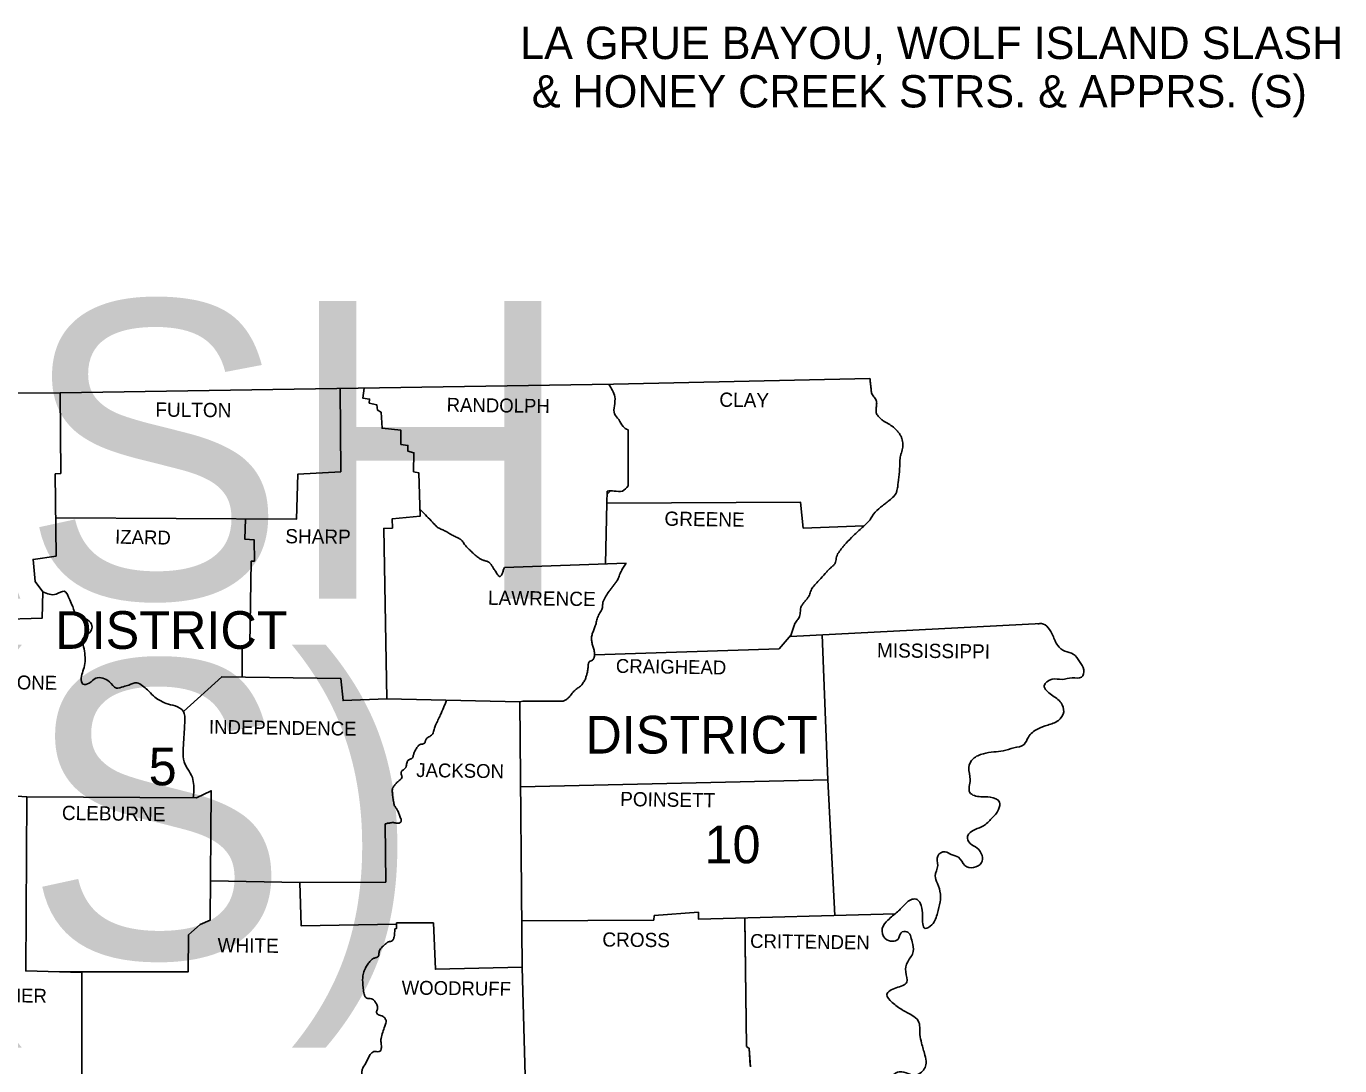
# Model space of a CAD drawing. Extents: x 982240 to 1103002, y 974866 to 1054902.
# Drawn here: x 1087558 to 1101862, y 1040761 to 1052081 of the extents above; entities that cross this region are included whole.
import ezdxf

# ---------------------------------------------------------------- set-up
doc = ezdxf.new("R2010")
doc.units = 0
for name, color, linetype in [('1', 7, 'Continuous'), ('Default', 7, 'Continuous'), ('R_Draft', 7, 'Continuous')]:
    doc.layers.add(name, color=color, linetype=linetype)

msp = doc.modelspace()

# ---------------------------------------------------------------- linework, layer by layer
at = {"layer": '1'}
for p, q in [((1095882, 1045436), (1095921, 1045555)), ((1091591, 1042318), (1091994, 1042318))]:
    msp.add_line(p, q, dxfattribs=at)
for points in [[(1076997, 1048082), (1082818, 1048078), (1087927, 1048089), (1093953, 1048183), (1096746, 1048247)], [(1091238, 1048140), (1091224, 1048031), (1091296, 1048021), (1091293, 1047977), (1091375, 1047959), (1091383, 1047902), (1091422, 1047877), (1091433, 1047704), (1091638, 1047682), (1091638, 1047527), (1091714, 1047517), (1091714, 1047455), (1091779, 1047437), (1091775, 1047229), (1091833, 1047218), (1091847, 1046746), (1091541, 1046717), (1091545, 1046617), (1091451, 1046613), (1091483, 1044755), (1092934, 1044723), (1092959, 1041836), (1092013, 1041811), (1091994, 1042318)], [(1087927, 1048089), (1087934, 1047211), (1087873, 1047207), (1087883, 1046311), (1087631, 1046275), (1087653, 1046033), (1087739, 1045922), (1087732, 1045637), (1087243, 1045619), (1087225, 1045180), (1086778, 1045166), (1086757, 1044633), (1086782, 1044590), (1086793, 1043740), (1087563, 1043690), (1087552, 1041793), (1088164, 1041775), (1088164, 1039845), (1087682, 1039809), (1087646, 1039384), (1086836, 1039381)], [(1095882, 1045436), (1098615, 1045576)], [(1092955, 1042340), (1094392, 1042347), (1094396, 1042397), (1094878, 1042433), (1094878, 1042358), (1097023, 1042417)], [(1091591, 1042318), (1091591, 1042257), (1091573, 1042253)]]:
    msp.add_lwpolyline(points, dxfattribs=at)
for points in [[(1096746, 1048247), (1096750, 1048208), (1096754, 1048168), (1096759, 1048128), (1096764, 1048089), (1096773, 1048067), (1096787, 1048047), (1096803, 1048027), (1096815, 1048006), (1096819, 1047970), (1096815, 1047930), (1096812, 1047891), (1096815, 1047872), (1096822, 1047855), (1096849, 1047820), (1096883, 1047790), (1096909, 1047773), (1096936, 1047758), (1096962, 1047743), (1096988, 1047725), (1097040, 1047679), (1097062, 1047652), (1097072, 1047637), (1097081, 1047621), (1097094, 1047591), (1097102, 1047560), (1097105, 1047529), (1097103, 1047499), (1097097, 1047467), (1097088, 1047436), (1097079, 1047404), (1097074, 1047373), (1097072, 1047338), (1097071, 1047302), (1097069, 1047267), (1097067, 1047232), (1097052, 1047110), (1097046, 1047053), (1097040, 1047026), (1097036, 1047012), (1097031, 1046998), (1096993, 1046948), (1096944, 1046908), (1096924, 1046892), (1096903, 1046876), (1096882, 1046860), (1096862, 1046843), (1096786, 1046768), (1096772, 1046748), (1096760, 1046728), (1096747, 1046707), (1096732, 1046689), (1096638, 1046602), (1096545, 1046512), (1096469, 1046433), (1096449, 1046409), (1096429, 1046384), (1096411, 1046358), (1096394, 1046332), (1096383, 1046305), (1096377, 1046275), (1096371, 1046246), (1096366, 1046233), (1096358, 1046221), (1096338, 1046200), (1096316, 1046181), (1096295, 1046162), (1096275, 1046141), (1096210, 1046069), (1096124, 1045972), (1096109, 1045950), (1096100, 1045925), (1096091, 1045899), (1096080, 1045875), (1096061, 1045847), (1096039, 1045820), (1096016, 1045793), (1095998, 1045763), (1095990, 1045738), (1095988, 1045710), (1095986, 1045682), (1095980, 1045655), (1095968, 1045633), (1095954, 1045612), (1095939, 1045591), (1095926, 1045569), (1095921, 1045555)], [(1098575, 1045573), (1098615, 1045576), (1098737, 1045447), (1098791, 1045339), (1098870, 1045277), (1098960, 1045245), (1099029, 1045162), (1099076, 1045072), (1099050, 1044993), (1098950, 1044986), (1098838, 1044968), (1098730, 1044971), (1098644, 1044899), (1098723, 1044802), (1098827, 1044712), (1098856, 1044615), (1098798, 1044521), (1098683, 1044471), (1098572, 1044428), (1098471, 1044341), (1098424, 1044259), (1098312, 1044223), (1098197, 1044190), (1098096, 1044179), (1097981, 1044158), (1097870, 1044104), (1097823, 1044010), (1097837, 1043877), (1097834, 1043737), (1097952, 1043690), (1098057, 1043686), (1098158, 1043632), (1098147, 1043553), (1098071, 1043452), (1097981, 1043373), (1097891, 1043333), (1097808, 1043258), (1097837, 1043182), (1097913, 1043132), (1097967, 1043049), (1097960, 1042973), (1097873, 1042919), (1097780, 1042941), (1097711, 1043031), (1097632, 1043060), (1097564, 1043092), (1097484, 1043045), (1097484, 1042941), (1097456, 1042829), (1097481, 1042747), (1097513, 1042631), (1097510, 1042545), (1097481, 1042423), (1097420, 1042297), (1097348, 1042257), (1097319, 1042394), (1097304, 1042505), (1097261, 1042570), (1097204, 1042574), (1097128, 1042520), (1097045, 1042437), (1096941, 1042347), (1096880, 1042257), (1096912, 1042145), (1096991, 1042117), (1097052, 1042138), (1097085, 1042210), (1097146, 1042221), (1097204, 1042109)], [(1091573, 1042253), (1091571, 1042223), (1091568, 1042194), (1091564, 1042164), (1091560, 1042149), (1091558, 1042142), (1091555, 1042135), (1091544, 1042121), (1091525, 1042115), (1091505, 1042110), (1091495, 1042107), (1091487, 1042102), (1091445, 1042065), (1091408, 1042023), (1091401, 1042006), (1091399, 1041986), (1091397, 1041967), (1091390, 1041951), (1091383, 1041945), (1091375, 1041941), (1091358, 1041936), (1091340, 1041931), (1091325, 1041922), (1091308, 1041905), (1091292, 1041887), (1091277, 1041868), (1091264, 1041847), (1091239, 1041796), (1091224, 1041742), (1091221, 1041688), (1091224, 1041634), (1091227, 1041603), (1091231, 1041572), (1091238, 1041542), (1091243, 1041527), (1091249, 1041512), (1091266, 1041497), (1091291, 1041493), (1091318, 1041490), (1091339, 1041479), (1091347, 1041471), (1091353, 1041463), (1091365, 1041445), (1091383, 1041407), (1091384, 1041389), (1091378, 1041369), (1091373, 1041350), (1091375, 1041332), (1091392, 1041316), (1091417, 1041307), (1091443, 1041298), (1091462, 1041281), (1091468, 1041271), (1091474, 1041260), (1091477, 1041249), (1091476, 1041238), (1091462, 1041191), (1091422, 1041058), (1091419, 1041036), (1091421, 1041014), (1091424, 1040991), (1091426, 1040968), (1091424, 1040948), (1091422, 1040938), (1091419, 1040929), (1091400, 1040915), (1091371, 1040915), (1091342, 1040915), (1091321, 1040903), (1091264, 1040806), (1091224, 1040738), (1091219, 1040727), (1091212, 1040693), (1091211, 1040670), (1091210, 1040648), (1091212, 1040632), (1091216, 1040615), (1091220, 1040599), (1091221, 1040583), (1091216, 1040570), (1091207, 1040557), (1091198, 1040545), (1091192, 1040533), (1091189, 1040514), (1091188, 1040494), (1091187, 1040475), (1091181, 1040457), (1091145, 1040392), (1091113, 1040331), (1091114, 1040313), (1091128, 1040295), (1091143, 1040277), (1091149, 1040259), (1091144, 1040234), (1091138, 1040209), (1091132, 1040189), (1091126, 1040169), (1091116, 1040129)], [(1097204, 1042109), (1097218, 1042005), (1097157, 1041893), (1097135, 1041782), (1097146, 1041670), (1097031, 1041609), (1096930, 1041537), (1096988, 1041451), (1097096, 1041371), (1097204, 1041310), (1097272, 1041249), (1097290, 1041101), (1097308, 1041008), (1097344, 1040878), (1097358, 1040788), (1097294, 1040680), (1097218, 1040659), (1097139, 1040684), (1097045, 1040691), (1096970, 1040619), (1096916, 1040518), (1096862, 1040417), (1096822, 1040331), (1096782, 1040237), (1096703, 1040129), (1096606, 1040111), (1096491, 1040083), (1096422, 1040003), (1096433, 1039870), (1096498, 1039780), (1096548, 1039669), (1096584, 1039571), (1096566, 1039449), (1096516, 1039359), (1096451, 1039305), (1096422, 1039190), (1096376, 1039103), (1096332, 1039075), (1096246, 1039082), (1096152, 1039100), (1096073, 1039093), (1095998, 1039053), (1095922, 1039078), (1095843, 1039165), (1095778, 1039229), (1095706, 1039255), (1095630, 1039215), (1095616, 1039096), (1095652, 1038974), (1095684, 1038808), (1095652, 1038707), (1095641, 1038542)]]:
    msp.add_spline(points, degree=3, dxfattribs=at)
at = {"layer": 'Default'}
msp.add_line((1093881, 1046887), (1093885, 1047020), dxfattribs=at)
for points in [[(1090976, 1048136), (1090983, 1047229), (1090515, 1047203), (1090501, 1046714), (1087878, 1046728)], [(1094111, 1047686), (1094111, 1047077)], [(1093866, 1046227), (1093881, 1046887), (1093885, 1046887), (1095990, 1046897), (1096019, 1046617), (1096680, 1046641)], [(1089947, 1046717), (1089939, 1046494), (1090040, 1046487), (1090043, 1046257), (1090007, 1046257), (1089993, 1045349), (1089910, 1045313), (1089910, 1044994)], [(1092765, 1046188), (1094092, 1046235)], [(1093746, 1045237), (1095756, 1045303), (1095889, 1045455)], [(1096227, 1045454), (1096289, 1043873), (1096362, 1042399)], [(1089269, 1044619), (1089687, 1044997), (1090983, 1044979), (1091008, 1044737), (1091483, 1044755)], [(1093406, 1044730), (1092967, 1044730), (1092934, 1044723)], [(1096289, 1043873), (1092942, 1043797)], [(1087563, 1043690), (1089413, 1043679), (1089572, 1043755), (1089561, 1042347), (1089453, 1042300), (1089356, 1042217), (1089323, 1042185), (1089320, 1041782), (1087919, 1041782)], [(1091465, 1043395), (1091473, 1042761), (1090537, 1042757), (1089564, 1042776)], [(1090537, 1042757), (1090551, 1042286), (1091591, 1042304)], [(1095382, 1042372), (1095400, 1040972), (1095432, 1040950), (1095444, 1040751)], [(1095382, 1042358), (1095400, 1040972), (1095432, 1040950), (1095443, 1040763)], [(1095382, 1042358), (1095400, 1040972), (1095432, 1040950), (1095443, 1040763)], [(1095382, 1042358), (1095400, 1040972), (1095432, 1040950), (1095443, 1040763)], [(1095382, 1042358), (1095400, 1040972), (1095432, 1040950), (1095443, 1040763)], [(1092959, 1041836), (1093013, 1039863), (1092157, 1039859), (1092153, 1039780), (1091905, 1039766), (1091883, 1039355), (1091542, 1039355)]]:
    msp.add_lwpolyline(points, dxfattribs=at)
for points in [[(1093902, 1048182), (1093967, 1048046), (1093964, 1047949), (1093964, 1047859), (1094011, 1047797), (1094057, 1047722), (1094111, 1047686)], [(1094111, 1047077), (1094050, 1047020), (1093960, 1047020), (1093885, 1047020)], [(1091845, 1046822), (1091905, 1046759), (1091966, 1046696), (1091974, 1046687), (1091999, 1046661), (1092016, 1046644), (1092025, 1046635), (1092030, 1046631), (1092034, 1046627), (1092053, 1046615), (1092073, 1046606), (1092093, 1046597), (1092113, 1046588), (1092160, 1046561), (1092207, 1046534), (1092228, 1046523), (1092249, 1046513), (1092280, 1046497), (1092285, 1046494), (1092290, 1046491), (1092306, 1046476), (1092318, 1046458), (1092330, 1046439), (1092337, 1046431), (1092344, 1046422), (1092381, 1046384), (1092419, 1046347), (1092438, 1046330), (1092456, 1046315), (1092476, 1046300), (1092495, 1046285), (1092524, 1046270), (1092557, 1046260), (1092588, 1046248), (1092602, 1046239), (1092608, 1046234), (1092614, 1046228), (1092624, 1046213), (1092634, 1046198), (1092643, 1046182), (1092653, 1046167), (1092660, 1046157), (1092667, 1046146), (1092680, 1046125), (1092694, 1046106), (1092701, 1046098), (1092704, 1046094), (1092706, 1046093), (1092707, 1046091), (1092711, 1046088), (1092715, 1046088), (1092724, 1046093), (1092739, 1046118), (1092753, 1046155), (1092759, 1046173), (1092765, 1046188)], [(1094092, 1046235), (1094062, 1046191), (1094036, 1046145), (1094024, 1046120), (1094015, 1046094), (1094005, 1046069), (1093993, 1046044), (1093972, 1046015), (1093950, 1045986), (1093928, 1045958), (1093906, 1045929), (1093871, 1045875), (1093856, 1045846), (1093841, 1045817), (1093836, 1045799), (1093835, 1045780), (1093834, 1045760), (1093831, 1045742), (1093819, 1045716), (1093805, 1045692), (1093791, 1045667), (1093780, 1045641), (1093773, 1045616), (1093766, 1045591), (1093759, 1045565), (1093751, 1045540), (1093744, 1045519), (1093735, 1045497), (1093726, 1045476), (1093719, 1045454), (1093715, 1045432), (1093714, 1045409), (1093716, 1045386), (1093719, 1045364), (1093724, 1045341), (1093731, 1045319), (1093739, 1045296), (1093744, 1045274), (1093746, 1045253), (1093746, 1045232), (1093743, 1045211), (1093740, 1045201), (1093737, 1045191), (1093726, 1045179), (1093709, 1045171), (1093693, 1045164), (1093683, 1045151), (1093680, 1045139), (1093678, 1045126), (1093676, 1045099), (1093673, 1045073), (1093669, 1045047), (1093659, 1045011), (1093647, 1044975), (1093627, 1044937), (1093614, 1044919), (1093600, 1044903), (1093584, 1044888), (1093566, 1044876), (1093548, 1044863), (1093532, 1044849), (1093513, 1044829), (1093496, 1044808), (1093479, 1044786), (1093460, 1044766), (1093435, 1044746), (1093421, 1044738), (1093406, 1044730)], [(1087739, 1045922), (1087883, 1045897), (1087970, 1045929), (1088031, 1045835), (1088063, 1045763), (1088117, 1045659), (1088204, 1045627), (1088269, 1045569), (1088269, 1045508), (1088211, 1045450), (1088168, 1045393), (1088182, 1045324), (1088197, 1045231), (1088197, 1045141), (1088175, 1045058), (1088157, 1044982), (1088175, 1044917), (1088243, 1044928), (1088315, 1044982), (1088391, 1044982), (1088463, 1044943), (1088539, 1044874), (1088614, 1044889), (1088675, 1044907), (1088762, 1044932), (1088823, 1044899), (1088877, 1044856), (1088942, 1044788), (1089003, 1044745), (1089082, 1044705), (1089179, 1044680), (1089269, 1044619), (1089284, 1044514), (1089280, 1044424), (1089273, 1044313), (1089266, 1044190), (1089277, 1044071), (1089316, 1043992), (1089367, 1043899), (1089381, 1043812), (1089377, 1043675)], [(1092134, 1044741), (1092102, 1044659), (1092067, 1044579), (1092054, 1044552), (1092041, 1044525), (1092029, 1044498), (1092016, 1044471), (1092007, 1044448), (1092000, 1044424), (1091993, 1044400), (1091984, 1044377), (1091970, 1044361), (1091952, 1044348), (1091932, 1044337), (1091923, 1044331), (1091915, 1044323), (1091909, 1044312), (1091905, 1044298), (1091901, 1044284), (1091894, 1044273), (1091880, 1044266), (1091863, 1044263), (1091846, 1044260), (1091833, 1044251), (1091826, 1044243), (1091819, 1044235), (1091807, 1044217), (1091796, 1044198), (1091786, 1044179), (1091780, 1044163), (1091775, 1044147), (1091771, 1044130), (1091764, 1044115), (1091754, 1044105), (1091740, 1044100), (1091725, 1044094), (1091714, 1044086), (1091709, 1044077), (1091705, 1044067), (1091700, 1044046), (1091696, 1044025), (1091691, 1044011), (1091689, 1044007), (1091678, 1043995), (1091665, 1043985), (1091652, 1043975), (1091642, 1043963), (1091640, 1043946), (1091645, 1043927), (1091650, 1043908), (1091645, 1043891), (1091642, 1043888), (1091639, 1043885), (1091619, 1043866), (1091605, 1043854), (1091591, 1043841), (1091579, 1043828), (1091567, 1043814), (1091556, 1043800), (1091552, 1043792), (1091548, 1043783), (1091544, 1043744), (1091548, 1043704), (1091551, 1043678), (1091554, 1043652), (1091559, 1043626), (1091562, 1043613), (1091566, 1043600), (1091574, 1043584), (1091583, 1043569), (1091593, 1043554), (1091602, 1043539), (1091620, 1043499), (1091627, 1043479), (1091635, 1043459), (1091639, 1043447), (1091641, 1043433), (1091639, 1043420), (1091636, 1043414), (1091634, 1043411), (1091631, 1043409), (1091609, 1043401), (1091586, 1043403), (1091563, 1043408), (1091552, 1043410), (1091541, 1043409), (1091522, 1043406), (1091503, 1043403), (1091484, 1043399), (1091465, 1043395)]]:
    msp.add_spline(points, degree=3, dxfattribs=at)
at = {"layer": 'R_Draft'}
msp.add_line((1093884, 1046985), (1093918, 1047020), dxfattribs=at)

# ---------------------------------------------------------------- texts
at = {"layer": '1'}
for s, p in [('LA GRUE BAYOU, WOLF ISLAND SLASH', (1092936, 1051724)), ('& HONEY CREEK STRS. & APPRS. (S)', (1093063, 1051197))]:
    msp.add_text(s, height=351.72, dxfattribs=at).set_placement(p)
at = {"layer": 'Default'}
for s, height, rotation, p in [('FULTON', 154.8, 359.4996, (1088963, 1047830)), ('RANDOLPH', 151.2, 359.2583, (1092135, 1047884)), ('CLAY', 154.8, 359.2258, (1095105, 1047938)), ('GREENE', 154.8, 359.2361, (1094507, 1046642)), ('IZARD', 151.2, 358.9258, (1088524, 1046447)), ('SHARP', 154.8, 359.3905, (1090378, 1046451)), ('LAWRENCE', 154.8, 359.2678, (1092585, 1045781)), ('MISSISSIPPI', 154.78, 359.3097, (1096822, 1045209)), ('CRAIGHEAD', 151.2, 359.1159, (1093978, 1045040)), ('STONE', 151.2, 359.4001, (1087196, 1044863)), ('INDEPENDENCE', 151.18, 359.2187, (1089547, 1044377)), ('JACKSON', 151.2, 359.1352, (1091804, 1043906)), ('POINSETT', 154.8, 359.1987, (1094025, 1043589)), ('CLEBURNE', 154.8, 359.2535, (1087945, 1043438)), ('WHITE', 154.8, 359.3138, (1089640, 1041998)), ('CROSS', 154.8, 359.3839, (1093831, 1042059)), ('CRITTENDEN', 151.2, 359.213, (1095440, 1042045)), ('WOODRUFF', 151.2, 359.2748, (1091645, 1041537)), ('FAULKNER', 151.2, 359.2486, (1086703, 1041461))]:
    msp.add_text(s, height=height, rotation=rotation, dxfattribs=at).set_placement(p)
for s, height, p in [('DISTRICT', 410.4, (1087873, 1045301)), ('DISTRICT', 410.4, (1093647, 1044161)), ('5', 410, (1088891, 1043815)), ('10', 410.4, (1094944, 1042966))]:
    msp.add_text(s, height=height, dxfattribs=at).set_placement(p)
at = {"layer": 'R_Draft'}
for s, p in [('LA GRUE BAYOU, WOLF ISLAND SLASH', (1010938, 1045849)), (' & HONEY CREEK STRS. & APPRS. (S)', (1012901, 1041933))]:
    msp.add_text(s, height=3240, dxfattribs=at).set_placement(p)

doc.saveas('drawing.dxf')
